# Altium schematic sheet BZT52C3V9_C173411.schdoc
size 127 x 101 mm
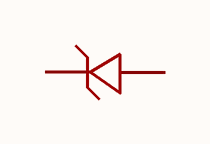
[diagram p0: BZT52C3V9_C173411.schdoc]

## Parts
D?  bzt52c3v9_c173411  [SOD-123FL_L2.7-W1.8-LS3.8-RD]  (value not drawn)

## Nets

Not connected (* = marked no-connect by the designer): D? 1(K) 2(A)

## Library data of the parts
D? = bzt52c3v9_c173411: 二极管配置:1个独立式;稳压值(标称值):3.9V;稳压值(范围值):3.71V~4.11V;耗散功率(Pd):500mW;; Manufacturer: MDD(辰达半导体); AddInBom: yes; ModelId: 86f9151e155e4fe2af0c4f2e0a80302e; ModelName: SOD-123FL_L2.8-W1.8-H1.1-LS3.6; ModelTransform: 141.732,70.866,0,180,0,0,0,0,0; Diode Configuration: 1个独立式; Zener Voltage(Nom): 3.9V; Reverse Leakage Current (Ir): 5uA@1V; Pd - Power Dissipation: 500mW; Impedance(Zzt): 130Ω; Tolerance: ±5%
